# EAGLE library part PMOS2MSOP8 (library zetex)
Dual MOS FET
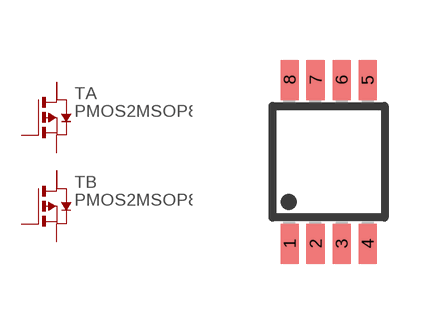
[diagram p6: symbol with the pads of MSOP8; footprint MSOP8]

Designator prefix T; gates A=P_MOS2D B=P_MOS2D

## PMOS2MSOP8 (OC_FARNELL: 1412091; OC_NEWARK: unknown)  [MSOP8]
1  A:S  pas
2  A:G  pas
3  B:S  pas
4  B:G  pas
5  B:D2  pas
6  B:D  pas
7  A:D  pas
8  A:D2  pas

## Footprint MSOP8 (pad centres in mm)
Micro Small Outline Package
smd 0.45 x 1: 1 -0.975,-2.05; 2 -0.325,-2.05; 3 0.325,-2.05; 4 0.975,-2.05; 5 0.975,2.05; 6 0.325,2.05; 7 -0.325,2.05; 8 -0.975,2.05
